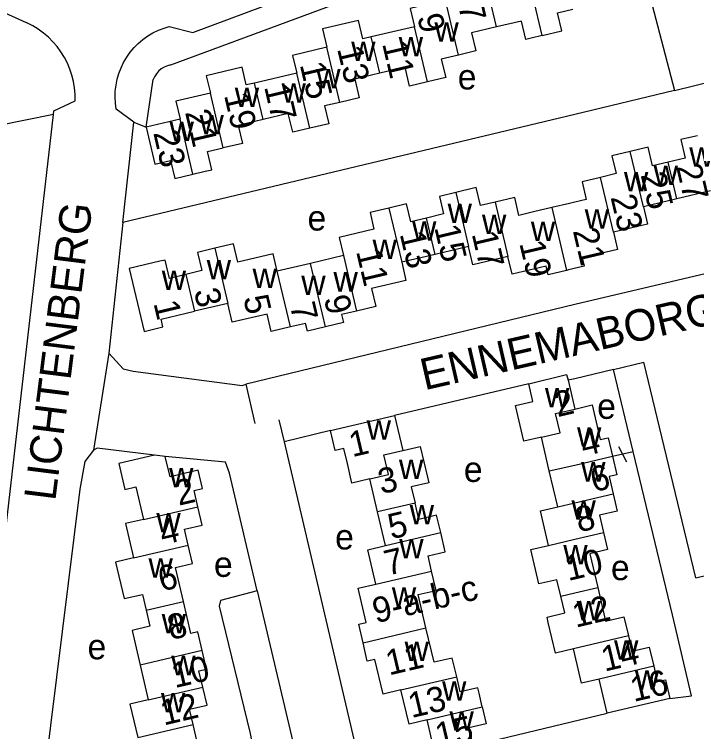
# Model space of a CAD drawing. Extents: x 157646 to 159241, y 379213 to 381217.
# Drawn here: x 159011 to 159119.4, y 380620.1 to 380734 of the extents above; entities that cross this region are included whole.
import ezdxf

# ---------------------------------------------------------------- set-up
doc = ezdxf.new("R2010")
doc.units = 0
for name, color, linetype in [('BLT_Basislijn', 7, 'Continuous'), ('BLT_Bebouwing', 7, 'Continuous'), ('BLT_Centroide', 7, 'Continuous'), ('BLT_Huisnummer', 7, 'Continuous'), ('BLT_Huisnummer_ tussenligend', 7, 'Continuous'), ('BLT_Huisnummer_reeks', 7, 'Continuous'), ('BLT_Onderverdeling_panden', 7, 'Continuous'), ('BLT_Straatnaam', 7, 'Continuous'), ('BLT_Vlakafsluiter', 7, 'Continuous')]:
    doc.layers.add(name, color=color, linetype=linetype)

msp = doc.modelspace()

# ---------------------------------------------------------------- linework, layer by layer
at = {"layer": 'BLT_Basislijn'}
for p, q in [((159035.86, 380725.94), (159107.8, 380752.64)), ((159107.8, 380752.64), (159115.84, 380721.89)), ((158996.99, 380739.89), (159012.87, 380732.66)), ((159115.84, 380721.89), (159140.92, 380727.95)), ((159031.94, 380716.04), (159033.05, 380723.6)), ((159017.28, 380718.62), (159020.67, 380720.23)), ((159030.01, 380716.82), (159027.21, 380718.92)), ((159017.21, 380718.06), (159003.99, 380715.39)), ((159008.5, 380642.51), (159017.21, 380718.06)), ((159017.21, 380718.06), (159017.28, 380718.62)), ((159028.23, 380700.89), (159030.01, 380716.82)), ((159030.01, 380716.82), (159031.94, 380716.04)), ((159106.13, 380677.54), (159110.99, 380678.71)), ((159119.24, 380644.51), (159110.99, 380678.71)), ((159049.23, 380669), (159047.85, 380675.22)), ((159092.69, 380675.28), (159071.39, 380670.28)), ((159053, 380669.56), (159053.86, 380666.07)), ((159061.24, 380667.86), (159053.86, 380666.07)), ((159106.94, 380665.36), (159108.2, 380662.91)), ((159106.01, 380663.8), (159109.26, 380664.57)), ((159119.24, 380644.51), (159152.47, 380652.46)), ((159049.58, 380642.43), (159063.51, 380583.63)), ((159118.52, 380625.74), (159115.53, 380638.59)), ((159115.12, 380625.33), (159118.52, 380625.74)), ((159083.82, 380617.89), (159105.15, 380622.99))]:
    msp.add_line(p, q, dxfattribs=at)
for points in [[(159035.62, 380732.02), (159039.36, 380731.08), (159088.22, 380749.33), (159087.76, 380751.2)], [(159020.67, 380720.23), (159020.66, 380721.26), (159020.57, 380722.28), (159020.4, 380723.3), (159020.16, 380724.29), (159019.83, 380725.27), (159019.44, 380726.21), (159018.96, 380727.12), (159018.42, 380728), (159017.82, 380728.83), (159017.15, 380729.6), (159016.42, 380730.33), (159015.64, 380730.99), (159014.81, 380731.6), (159013.93, 380732.13), (159013.02, 380732.6), (159012.87, 380732.66)], [(159027.21, 380718.92), (159027.08, 380719.87), (159027.02, 380720.82), (159027.05, 380721.78), (159027.16, 380722.73), (159027.35, 380723.66), (159027.62, 380724.58), (159027.96, 380725.47), (159028.37, 380726.33), (159028.86, 380727.16), (159029.41, 380727.94), (159030.02, 380728.67), (159030.7, 380729.34), (159031.43, 380729.96), (159032.21, 380730.52), (159033.03, 380731.01), (159033.89, 380731.42), (159034.78, 380731.77), (159035.62, 380732.02)], [(159035.86, 380725.94), (159035.33, 380725.79), (159034.82, 380725.57), (159034.35, 380725.28), (159033.93, 380724.93), (159033.57, 380724.52), (159033.27, 380724.05), (159033.05, 380723.6)], [(159115.84, 380721.89), (159100, 380718.08), (159028.23, 380700.89)], [(159028.23, 380700.89), (159026.01, 380680.16)], [(159138.5, 380696.95), (159138.02, 380696.85), (159100, 380687.87), (159047.85, 380675.22)], [(159026.01, 380680.16), (159028.3, 380677.66), (159029.86, 380677.28), (159047.21, 380675.02), (159047.85, 380675.22)], [(159106.13, 380677.54), (159100, 380676.1), (159098.93, 380675.85)], [(159109.26, 380664.57), (159106.13, 380677.54)], [(159053.86, 380666.07), (159054.03, 380665.37), (159066.13, 380613.61)], [(159023.56, 380664.77), (159022.19, 380662.96), (159021.43, 380658.55), (159014.88, 380606.1)], [(159033.27, 380663.97), (159024.19, 380665.06), (159023.56, 380664.77)], [(159115.53, 380638.59), (159109.26, 380664.57)], [(159049.58, 380642.43), (159045.16, 380661.11), (159044.52, 380662.86), (159034.98, 380663.76)], [(159049.58, 380642.43), (159043.73, 380640.87), (159043.54, 380640), (159048.46, 380619.78), (159049.43, 380614.74), (159049.11, 380614.39), (159038.55, 380611.98)]]:
    msp.add_lwpolyline(points, dxfattribs=at)
at = {"layer": 'BLT_Bebouwing'}
for p, q in [((159074.56, 380731.99), (159067.7, 380730.38)), ((159055.86, 380724.63), (159049.17, 380723.05)), ((159037.32, 380717.32), (159031.94, 380716.04)), ((159121.54, 380705.91), (159116.22, 380704.66)), ((159116.22, 380704.66), (159110.9, 380703.4)), ((159096.37, 380703.27), (159093.43, 380702.58)), ((159099.14, 380703.92), (159096.37, 380703.27)), ((159083.15, 380697.09), (159077.84, 380695.84)), ((159063.27, 380695.64), (159058.03, 380694.41)), ((159077.84, 380695.84), (159072.53, 380694.59)), ((159058.03, 380694.41), (159052.75, 380693.16)), ((159044.91, 380688.07), (159039.6, 380686.82)), ((159061.24, 380667.86), (159071.39, 380670.28)), ((159071.39, 380670.28), (159072.72, 380664.71)), ((159095.96, 380661.46), (159094.7, 380666.83)), ((159097.3, 380655.76), (159095.96, 380661.46)), ((159030.98, 380630.64), (159032.28, 380625.11)), ((159105.15, 380622.99), (159103.88, 380628.42)), ((159115.12, 380625.33), (159105.15, 380622.99)), ((159077.81, 380616.48), (159076.54, 380621.92))]:
    msp.add_line(p, q, dxfattribs=at)
for points in [[(159079.49, 380736.22), (159073.88, 380734.89), (159074.56, 380731.99)], [(159094.85, 380730.58), (159097.96, 380731.32), (159097.28, 380734.21), (159099.68, 380734.77)], [(159067.7, 380730.38), (159066.37, 380730.06), (159065.68, 380732.99), (159059.94, 380731.64), (159060.63, 380728.72)], [(159094.85, 380730.58), (159093.1, 380730.17), (159092.22, 380729.96), (159091.53, 380732.89), (159087.56, 380731.95)], [(159087.56, 380731.95), (159083.6, 380731.02), (159084.27, 380728.15), (159081.54, 380727.5)], [(159060.63, 380728.72), (159055.2, 380727.44), (159055.86, 380724.63)], [(159081.54, 380727.5), (159078.81, 380726.86), (159079.51, 380723.91), (159076.63, 380723.23)], [(159049.17, 380723.05), (159047.85, 380722.74), (159047.18, 380725.55), (159041.49, 380724.21), (159042.14, 380721.44)], [(159069.06, 380724.63), (159065.07, 380723.69), (159065.77, 380720.71), (159062.69, 380719.98)], [(159076.63, 380723.23), (159073.76, 380722.55), (159073.05, 380725.57), (159069.06, 380724.63)], [(159042.14, 380721.44), (159036.66, 380720.15), (159037.32, 380717.32)], [(159062.69, 380719.98), (159060.27, 380719.41), (159060.93, 380716.58), (159057.93, 380715.87)], [(159057.93, 380715.87), (159055.21, 380715.23), (159054.5, 380718.2), (159050.53, 380717.26)], [(159050.53, 380717.26), (159046.56, 380716.32), (159047.24, 380713.47), (159044.19, 380712.75)], [(159031.94, 380716.04), (159033.3, 380710.16), (159035.8, 380710.75), (159036.48, 380707.89), (159039.38, 380708.58)], [(159119.47, 380714.68), (159117.81, 380714.29), (159116.83, 380714.06), (159117.52, 380711.11), (159114.85, 380710.48)], [(159039.38, 380708.58), (159041.34, 380709.04), (159042.39, 380709.29), (159041.71, 380712.17), (159044.19, 380712.75)], [(159108.82, 380712.2), (159105.9, 380711.51), (159106.57, 380708.66), (159104.07, 380708.07)], [(159114.85, 380710.48), (159112.35, 380709.89), (159111.65, 380712.87), (159108.82, 380712.2)], [(159104.07, 380708.07), (159101.16, 380707.38), (159101.82, 380704.56), (159100, 380704.13), (159099.14, 380703.92)], [(159087.37, 380704.14), (159085.01, 380703.58), (159084.34, 380706.44), (159081.12, 380705.68)], [(159081.12, 380705.68), (159078.51, 380705.06), (159079.17, 380702.26), (159076.47, 380701.62)], [(159093.43, 380702.58), (159091.14, 380702.04), (159090.47, 380704.87), (159087.37, 380704.14)], [(159070.5, 380703.2), (159067.49, 380702.49), (159068.12, 380699.84), (159062.59, 380698.53), (159063.27, 380695.64)], [(159076.47, 380701.62), (159073.95, 380701.03), (159073.29, 380703.86), (159070.5, 380703.2)], [(159110.9, 380703.4), (159111.55, 380700.64), (159106.13, 380699.36)], [(159106.13, 380699.36), (159106.78, 380696.61), (159101.17, 380695.28)], [(159052.75, 380693.16), (159052.09, 380695.95), (159046.5, 380694.63), (159045.82, 380697.51), (159042.85, 380696.81)], [(159042.85, 380696.81), (159040.12, 380696.16), (159040.81, 380693.26), (159038.23, 380692.65)], [(159089.4, 380695.49), (159083.84, 380694.17), (159083.15, 380697.09)], [(159038.23, 380692.65), (159035.65, 380692.04), (159034.96, 380694.93), (159034.12, 380694.74), (159029.26, 380693.59), (159031.61, 380683.61), (159034.61, 380684.32), (159034.32, 380685.57), (159039.6, 380686.82)], [(159095.46, 380693.99), (159090.06, 380692.72), (159089.4, 380695.49)], [(159101.17, 380695.28), (159101.49, 380693.96), (159099.03, 380693.38), (159098.71, 380693.3)], [(159072.53, 380694.59), (159073.2, 380691.72), (159067.74, 380690.43), (159068.42, 380687.56), (159065.35, 380686.84)], [(159098.71, 380693.3), (159095.78, 380692.61), (159095.46, 380693.99)], [(159054.84, 380684.32), (159051.8, 380683.6), (159051.15, 380686.37), (159045.62, 380685.06), (159044.91, 380688.07)], [(159065.35, 380686.84), (159062.98, 380686.28), (159063.28, 380685.01), (159060.41, 380684.33)], [(159060.41, 380684.33), (159057.54, 380683.66), (159057.25, 380684.89), (159054.84, 380684.32)], [(159092.69, 380675.28), (159098.71, 380676.77), (159098.93, 380675.85)], [(159098.93, 380675.85), (159100.02, 380671.29)], [(159094.7, 380666.83), (159091.91, 380666.19), (159090.57, 380671.84), (159093.34, 380672.49), (159092.69, 380675.28)], [(159100.02, 380671.29), (159102.77, 380671.94), (159103.42, 380669.19)], [(159103.42, 380669.19), (159104.06, 380666.43), (159105.33, 380666.73), (159106.01, 380663.8)], [(159063.89, 380662.64), (159063.33, 380665.04), (159061.98, 380664.72), (159061.24, 380667.86)], [(159072.72, 380664.71), (159075.48, 380665.35), (159076.62, 380660.49), (159076.83, 380659.59), (159074.04, 380658.94), (159074.65, 380656.35)], [(159033.27, 380663.97), (159027.6, 380662.64), (159028.57, 380658.51), (159030.31, 380658.91), (159031.52, 380653.75)], [(159034.98, 380663.76), (159033.27, 380663.97)], [(159035.74, 380660.53), (159034.98, 380663.76)], [(159106.01, 380663.8), (159106.7, 380660.86), (159105.46, 380660.58), (159106.11, 380657.82)], [(159067.46, 380660.2), (159064.62, 380659.54), (159063.89, 380662.64)], [(159040.15, 380655.78), (159039.55, 380658.33), (159040.9, 380658.65), (159040.21, 380661.58), (159035.74, 380660.53)], [(159068.69, 380654.96), (159067.46, 380660.2)], [(159106.11, 380657.82), (159106.75, 380655.07), (159103.94, 380654.41), (159104.58, 380651.68)], [(159078.72, 380651.66), (159078.07, 380654.43), (159075.25, 380653.77), (159074.65, 380656.35)], [(159038.63, 380649.67), (159038.03, 380652.2), (159040.84, 380652.86), (159040.15, 380655.78)], [(159095.82, 380649.63), (159094.54, 380655.11), (159097.3, 380655.76)], [(159069.94, 380649.6), (159068.69, 380654.96)], [(159031.52, 380653.75), (159028.68, 380653.09), (159029.96, 380647.64)], [(159077.28, 380645.56), (159076.71, 380647.99), (159079.43, 380648.63), (159078.72, 380651.66)], [(159104.58, 380651.68), (159105.22, 380648.96), (159102.39, 380648.29), (159103.64, 380642.96)], [(159037.86, 380640.71), (159036.59, 380646.14), (159039.3, 380646.78), (159038.63, 380649.67)], [(159068.41, 380643.48), (159067.13, 380648.95), (159069.94, 380649.6)], [(159097.77, 380641.58), (159097.16, 380644.19), (159094.3, 380643.52), (159093.02, 380648.98), (159095.82, 380649.63)], [(159029.96, 380647.64), (159027.1, 380646.97), (159028.45, 380641.18), (159031.36, 380641.86), (159031.95, 380639.33)], [(159076.38, 380636.53), (159075.15, 380641.82), (159078, 380642.49), (159077.28, 380645.56)], [(159066.38, 380634.19), (159065.69, 380637.13), (159066.9, 380637.41), (159065.63, 380642.83), (159068.41, 380643.48)], [(159103.64, 380642.96), (159104.89, 380637.62), (159107.81, 380638.3), (159108.52, 380635.26)], [(159099.79, 380633.22), (159096.94, 380632.55), (159095.8, 380637.42), (159095.6, 380638.26), (159098.4, 380638.91), (159097.77, 380641.58)], [(159040.85, 380632.95), (159040.16, 380635.9), (159039.05, 380635.64), (159037.86, 380640.71)], [(159031.95, 380639.33), (159032.55, 380636.79), (159029.7, 380636.12), (159030.98, 380630.64)], [(159081.26, 380628.78), (159080.56, 380631.75), (159077.66, 380631.07), (159076.38, 380636.53)], [(159108.52, 380635.26), (159109.09, 380632.83), (159111.83, 380633.47), (159112.54, 380630.45)], [(159072.41, 380626.71), (159069.57, 380626.04), (159068.28, 380631.54), (159067.06, 380631.25), (159066.38, 380634.19)], [(159040.94, 380627.14), (159040.33, 380629.72), (159041.54, 380630), (159040.85, 380632.95)], [(159103.88, 380628.42), (159101.07, 380627.76), (159100, 380632.33), (159099.79, 380633.22)], [(159112.54, 380630.45), (159113.11, 380628.01), (159114.43, 380628.31), (159115.12, 380625.33)], [(159085.31, 380623.98), (159084.8, 380626.19), (159084.6, 380627.01), (159081.82, 380626.36), (159081.26, 380628.78)], [(159039.41, 380621.19), (159038.84, 380623.64), (159041.61, 380624.29), (159040.94, 380627.14)], [(159076.54, 380621.92), (159073.69, 380621.25), (159072.41, 380626.71)], [(159032.28, 380625.11), (159029.36, 380624.42), (159030.6, 380619.12)], [(159085.31, 380623.98), (159085.94, 380621.32), (159083.17, 380620.67), (159083.82, 380617.89)], [(159038.55, 380611.98), (159037.26, 380617.49), (159040.12, 380618.16), (159039.41, 380621.19)]]:
    msp.add_lwpolyline(points, dxfattribs=at)
at = {"layer": 'BLT_Onderverdeling_panden'}
for p, q in [((159094.85, 380730.58), (159092.8, 380739.29)), ((159087.56, 380731.95), (159086.2, 380737.74)), ((159081.54, 380727.5), (159079.49, 380736.22)), ((159076.63, 380723.23), (159074.56, 380731.99)), ((159069.06, 380724.63), (159067.7, 380730.38)), ((159062.69, 380719.98), (159060.63, 380728.72)), ((159057.93, 380715.87), (159055.86, 380724.63)), ((159050.53, 380717.26), (159049.17, 380723.05)), ((159044.19, 380712.75), (159042.14, 380721.44)), ((159039.38, 380708.58), (159037.32, 380717.32)), ((159110.9, 380703.4), (159108.82, 380712.2)), ((159116.22, 380704.66), (159114.85, 380710.48)), ((159106.13, 380699.36), (159104.07, 380708.07)), ((159081.12, 380705.68), (159083.15, 380697.09)), ((159087.37, 380704.14), (159089.4, 380695.49)), ((159070.5, 380703.2), (159072.53, 380694.59)), ((159096.37, 380703.27), (159098.71, 380693.3)), ((159077.84, 380695.84), (159076.47, 380701.62)), ((159042.85, 380696.81), (159044.91, 380688.07)), ((159063.27, 380695.64), (159065.35, 380686.84)), ((159060.41, 380684.33), (159058.03, 380694.41)), ((159038.23, 380692.65), (159039.6, 380686.82)), ((159054.84, 380684.32), (159052.75, 380693.16)), ((159074.65, 380656.35), (159068.69, 380654.96)), ((159031.52, 380653.75), (159040.15, 380655.78)), ((159069.94, 380649.6), (159078.72, 380651.66)), ((159029.96, 380647.64), (159038.63, 380649.67)), ((159068.41, 380643.48), (159077.28, 380645.56)), ((159031.95, 380639.33), (159037.86, 380640.71)), ((159066.38, 380634.19), (159076.38, 380636.53)), ((159108.52, 380635.26), (159099.79, 380633.22)), ((159040.85, 380632.95), (159030.98, 380630.64)), ((159112.54, 380630.45), (159103.88, 380628.42)), ((159072.41, 380626.71), (159081.26, 380628.78)), ((159032.28, 380625.11), (159040.94, 380627.14)), ((159076.54, 380621.92), (159085.31, 380623.98)), ((159030.6, 380619.12), (159039.41, 380621.19))]:
    msp.add_line(p, q, dxfattribs=at)
for points in [[(159094.7, 380666.83), (159097.66, 380667.52), (159096.95, 380670.57), (159100.02, 380671.29)], [(159067.46, 380660.2), (159070.42, 380660.89), (159069.69, 380664), (159072.72, 380664.71)], [(159095.96, 380661.46), (159100, 380662.39), (159106.01, 380663.8)], [(159097.3, 380655.76), (159100, 380656.39), (159106.11, 380657.82)], [(159095.82, 380649.63), (159100, 380650.61), (159104.58, 380651.68)], [(159097.77, 380641.58), (159100, 380642.1), (159103.64, 380642.96)]]:
    msp.add_lwpolyline(points, dxfattribs=at)
at = {"layer": 'BLT_Vlakafsluiter'}
msp.add_line((159026.01, 380680.16), (159023.56, 380664.77), dxfattribs=at)

# ---------------------------------------------------------------- texts
at = {"layer": 'BLT_Centroide'}
for s, p in [('w', (159077.72, 380729.64)), ('w', (159072.05, 380727.28)), ('w', (159064.5, 380726.56)), ('w', (159058.95, 380722.2)), ('e', (159081.42, 380722.03)), ('w', (159046.02, 380719.23)), ('w', (159053.44, 380719.94)), ('w', (159040.42, 380714.92)), ('w', (159035.66, 380713.83)), ('w', (159118.19, 380709.75)), ('w', (159112.52, 380706.86)), ('w', (159107.81, 380705.86)), ('w', (159079.81, 380700.84)), ('w', (159101.58, 380699.94)), ('e', (159057.57, 380699.63)), ('w', (159085.27, 380699.06)), ('w', (159074.17, 380698.03)), ('w', (159093.03, 380697.95)), ('w', (159067.89, 380695.12)), ('w', (159041.56, 380691.89)), ('w', (159034.42, 380690.2)), ('w', (159048.84, 380690.5)), ('w', (159061.69, 380689.95)), ('w', (159056.58, 380689.39)), ('w', (159095.27, 380671.56)), ('e', (159103.56, 380669.73)), ('w', (159066.96, 380666.41)), ('w', (159100.36, 380665.31)), ('w', (159072.09, 380660.16)), ('w', (159035.59, 380658.88)), ('e', (159082.39, 380659.71)), ('w', (159101.01, 380659.78)), ('w', (159099.48, 380653.72)), ('w', (159073.79, 380652.97)), ('w', (159033.57, 380651.72)), ('e', (159061.95, 380648.99)), ('w', (159072.13, 380647.56)), ('w', (159098.18, 380646.62)), ('w', (159032.32, 380644.5)), ('e', (159042.71, 380644.64)), ('e', (159105.75, 380644.12)), ('w', (159070.96, 380639.88)), ('w', (159100.29, 380637.75)), ('w', (159034.41, 380635.69)), ('e', (159022.64, 380631.55)), ('w', (159106.24, 380631.5)), ('w', (159072.98, 380631.28)), ('w', (159035.93, 380629.03)), ('w', (159109.54, 380626.72)), ('w', (159078.93, 380625)), ('w', (159034.3, 380623.12)), ('w', (159080.11, 380620.22))]:
    msp.add_text(s, height=4, dxfattribs=at).set_placement(p)
at = {"layer": 'BLT_Huisnummer'}
for s, rotation, p in [('9', 283.2802, (159074.96, 380733.61)), ('13', 283.2844, (159062.25, 380728.51)), ('17', 283.2661, (159050.66, 380722.46)), ('23', 283.0444, (159033.06, 380715.16)), ('25', 283.2773, (159110.44, 380708.48)), ('21', 283.2773, (159099.68, 380699.6)), ('13', 283.2773, (159072.19, 380699.1)), ('17', 283.2773, (159083.62, 380699.11)), ('5', 283.2773, (159047.34, 380688.95)), ('9', 283.2773, (159060.14, 380688.91)), ('1', 283.2773, (159033.09, 380688.11)), ('2', 13.1882, (159097.27, 380669.99)), ('1', 13.184, (159064.68, 380663.64)), ('6', 13.1882, (159103, 380658.06)), ('2', 13.1767, (159037.11, 380655.92)), ('5', 13.184, (159070.86, 380650.59)), ('10', 13.1882, (159098.95, 380643.97)), ('6', 13.1767, (159034.36, 380642.3)), ('10', 13.1767, (159036.5, 380626.96)), ('16', 13.1812, (159109.35, 380624.77)), ('15', 13.184, (159078.38, 380617.42))]:
    msp.add_text(s, height=4, rotation=rotation, dxfattribs=at).set_placement(p)
at = {"layer": 'BLT_Huisnummer_ tussenligend'}
for s, rotation, p in [('7', 283.2786, (159081.46, 380735.36)), ('11', 283.2802, (159069.4, 380729.31)), ('15', 283.2844, (159056.32, 380725.98)), ('19', 283.2661, (159044.29, 380721.12)), ('21', 283.2661, (159038.1, 380718.43)), ('27', 283.2773, (159116.07, 380709.82)), ('23', 283.2773, (159105.66, 380704.93)), ('15', 283.2773, (159077.68, 380700.13)), ('19', 283.2773, (159091.18, 380697.62)), ('11', 283.2773, (159065.26, 380696.32)), ('3', 283.2773, (159039.51, 380690.03)), ('7', 283.2773, (159054.74, 380687.77)), ('4', 13.1882, (159101.41, 380663.76)), ('3', 13.184, (159069.28, 380657.75)), ('8', 13.1882, (159100.64, 380651.68)), ('4', 13.1767, (159034.58, 380649.68)), ('7', 13.184, (159070.26, 380644.81)), ('12', 13.1882, (159100.15, 380636.56)), ('8', 13.1767, (159035.85, 380634.59)), ('14', 13.1882, (159104.73, 380629.58)), ('11', 13.184, (159070.51, 380628.98)), ('13', 13.184, (159074.07, 380622.21)), ('12', 13.1767, (159034.74, 380621.03))]:
    msp.add_text(s, height=4, rotation=rotation, dxfattribs=at).set_placement(p)
at = {"layer": 'BLT_Huisnummer_reeks'}
msp.add_text('9-a-b-c', height=4, rotation=13.184, dxfattribs=at).set_placement((159068.41, 380637.26))
at = {"layer": 'BLT_Straatnaam'}
for s, rotation, p in [('LICHTENBERG', 82.8363, (159017.51, 380656.6)), ('ENNEMABORG', 12.8997, (159076.14, 380674.25))]:
    msp.add_text(s, height=5, rotation=rotation, dxfattribs=at).set_placement(p)

doc.saveas('drawing.dxf')
